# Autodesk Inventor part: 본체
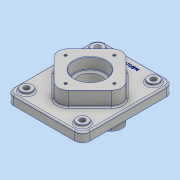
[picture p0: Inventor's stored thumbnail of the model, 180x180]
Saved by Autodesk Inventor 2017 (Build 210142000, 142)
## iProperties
Part Number: 본체
Material: 알루미늄 6061
Document SubType Name: Modeling
Designer: MRC
Density: 2.7 g/cm^3
Appearance: 알루미늄 - 평지
Mass: 2181.54 g
Surface Area: 961.758 cm^2
Volume: 807.977 cm^3
Author: MRC
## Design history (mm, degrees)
sketch "스케치1"
  geometry: L1 (75, -90)-(-75, -90); L2 (-75, -90)-(-75, 90); L3 (-75, 90)-(75, 90); L4 (75, 90)-(75, -90); L5 (75, -90)-(-75, 90); L6 (-75, -90)-(75, 90); 1 further point
  constraints: 12 end point, 2 midpoint, 2 parallel, 1 horizontal, 1 perpendicular
  dimensions: "d0" = 150 distance of L2.end L3.end; "d1" = 180 distance of L1.end L2.end
extrude "돌출1" new body sketch "스케치1" distance "d2" = 18; taper "d3" = 0 deg
fillet "모깎기1" dims "d4" = 15
sketch "스케치2"
  geometry: L1 (0, 70.711)-(70.711, 0); L2 (70.711, 0)-(0, -70.711); L3 (0, -70.711)-(-70.711, 0); L4 (-70.711, 0)-(0, 70.711); 2 further points
  constraints: 8 end point, 1 coincident, 1 vertical alignment, 9 other
  dimensions: "d5" = 100 distance between parallel lines of L2 L4
extrude "돌출2" join sketch "스케치2" distance "d6" = 29; taper "d8" = 0 deg; dims "d7" = 41, "d9" = 0
fillet "모깎기2" dims "d10" = 20
sketch "스케치3"
  geometry: 2 further points
  constraints: 1 coincident
hole "구멍1" sketch "스케치3" at (0, 0) diameter "d11" = 45; stored, may be unused: countersink angle "d15" = 90 deg, drill point angle "d17" = 118 deg; dims "d12" = 6, "d13" = 62, "d14" = 22, "d16" = 8
sketch "스케치4"
  geometry: C1 r 31 at (0, 0); 1 further point
  constraints: 1 centre point, 1 coincident
  dimensions: "d18" = 62 diameter of C1
extrude "돌출3" cut sketch "스케치4" distance "d19" = 22; taper "d20" = 0 deg
sketch "스케치5"
  geometry: 2 further points
  constraints: 1 vertical alignment
  dimensions: "d21" = 48 distance of point (0, 48) point (0, 0)
hole "구멍2" sketch "스케치5" at (0, 48) diameter "d22" = 4.917; stored, may be unused: countersink angle "d26" = 90 deg, drill point angle "d28" = 118 deg; dims "d23" = 10, "d24" = 62, "d25" = 22, "d27" = 13
node "작업 평면1"
sketch "스케치6"
  geometry: C1 r 11 at (55, 70); 1 further point
  constraints: 1 centre point
  dimensions: "d32" = 22 diameter of C1; "d46" = 55 horizontal distance of C1.centre point (0, 0); "d47" = 70 vertical distance of point (0, 0) C1.centre
extrude "돌출4" join sketch "스케치6" distance "d33" = 5; taper "d34" = 0 deg
sketch "스케치7"
  geometry: C1 r 5.5 at (0, 0); C2 r 11 at (0, 0) reference; 1 further point
  constraints: 1 centre point, 1 concentric
  dimensions: "d35" = 11 diameter of C1
extrude "돌출5" cut sketch "스케치7" stored distance "d36" = 5; taper "d37" = 0 deg
sketch "스케치8"
  geometry: L1 (60, 90)-(-60, 90) reference; 2 further points
  constraints: 1 vertical alignment, 1 other
  dimensions: "d38" = 15 distance from line of point (0, 75) L1
feature "엠보싱1" sketch "스케치8" dims "d0" = 150, "d1" = 180, "d10" = 20, "d39" = 0.5, "d40" = 0
fillet "모깎기3" dims "d41" = 3
fillet "모깎기4" dims "d42" = 1
chamfer "모따기1" distance "d43" = 1; stored, may be unused: second distance "d44" = 2, angle "d45" = 45 deg
fillet "모깎기5" dims "d48" = 3
node "솔리드1"
pattern_circular "원형 패턴1" dims angle "d30" = 360 deg
mirror "미러1"
mirror "미러2"
mirror "미러3"
